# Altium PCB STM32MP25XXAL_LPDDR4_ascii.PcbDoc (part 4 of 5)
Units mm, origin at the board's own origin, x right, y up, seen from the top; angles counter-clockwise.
Board outline 125 x 95 mm, 6 copper layers (Top Layer, Signal Layer 1, Signal Layer 2, Signal Layer 3, Signal Layer 4, Bottom Layer), stack 1.403 mm thick; 182 components, 297 nets, 1131 pads, 958 vias.
Unrouted connection lines stored in the file: 5.
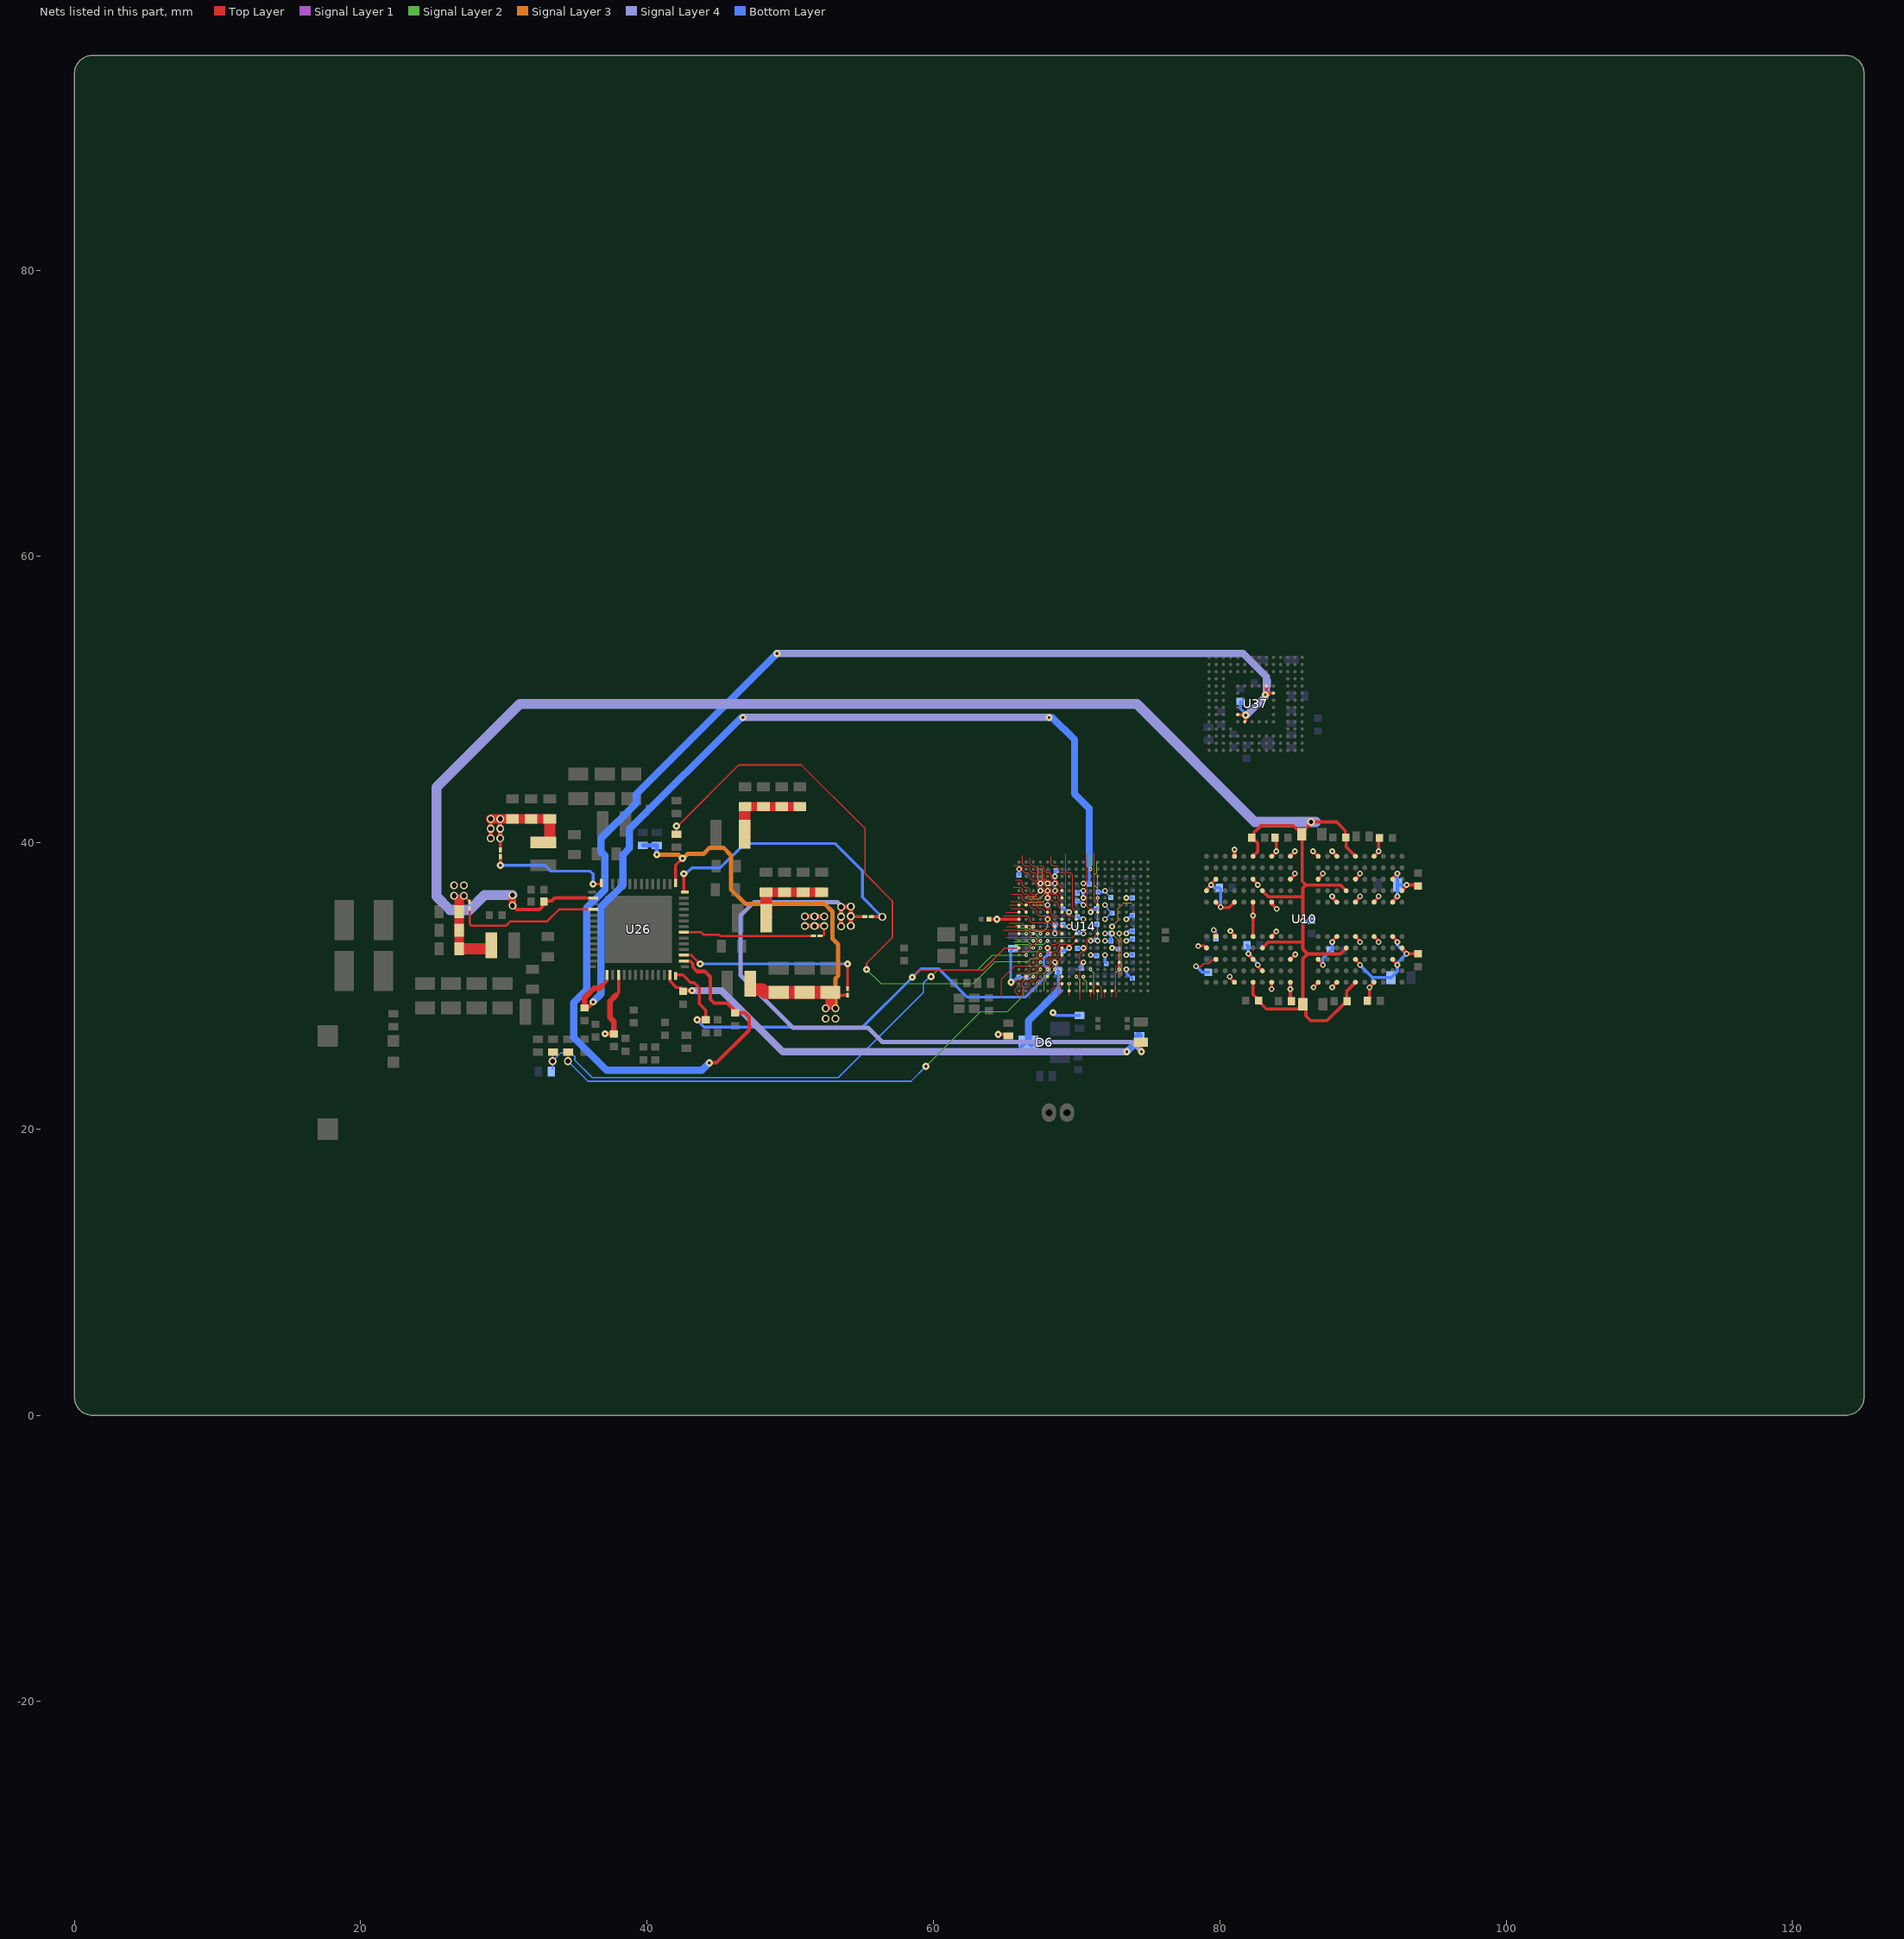
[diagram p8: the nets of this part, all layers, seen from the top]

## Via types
v1: diameter 0.26, hole 0.1, Top Layer to Signal Layer 1, 266 vias
v2: diameter 0.5, hole 0.2, Top Layer to Bottom Layer, 216 vias
v3: diameter 0.26, hole 0.1, Signal Layer 1 to Signal Layer 2, 138 vias
v4: diameter 0.4, hole 0.2, Signal Layer 1 to Signal Layer 4, 99 vias
v5: diameter 0.4, hole 0.2, Top Layer to Bottom Layer, tented both sides, 94 vias
v6: diameter 0.26, hole 0.1, Signal Layer 4 to Bottom Layer, 82 vias
v7: diameter 0.55, hole 0.35, Top Layer to Bottom Layer, 55 vias
v8: diameter 0.55, hole 0.3, Top Layer to Bottom Layer, 7 vias
v9: diameter 0.5, hole 0.2, Signal Layer 1 to Signal Layer 4, 1 vias

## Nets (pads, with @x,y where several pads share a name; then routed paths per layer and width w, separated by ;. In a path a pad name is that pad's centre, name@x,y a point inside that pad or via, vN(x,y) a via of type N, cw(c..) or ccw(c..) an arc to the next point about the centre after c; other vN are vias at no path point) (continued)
PF5: U14.P7 | length 5
  Top Layer w0.075: 66.2,29.125 66.2,29.416 66.224,29.44 66.224,29.755 66.367,29.897 66.575,29.897 66.725,30.048 66.725,30.253 66.873,30.401 67.078,30.401 67.225,30.547 67.225,30.753 67.372,30.899 67.66,30.899 67.662,30.897 68.074,30.897 68.224,31.047 68.224,31.252 68.372,31.4 68.577,31.4 68.732,31.555 68.732,31.75 68.968,31.986 68.968,32.143 U14.P7@68.975,32.15
PF6: U14.U5 | length 2.3
  Top Layer w0.075: 66.725,29.15 66.74,29.165 66.74,29.542 66.732,29.55 66.732,29.75 66.875,29.892 66.886,29.892 66.891,29.897 67.075,29.897 67.225,30.047 67.225,30.253 67.372,30.4 67.578,30.4 67.816,30.638 67.963,30.638 U14.U5@67.975,30.65
PF7: U14.V7 | length 1
  Top Layer w0.075: 68.7,29.25 68.732,29.282 68.732,29.761 68.962,29.991 68.962,30.137 U14.V7@68.975,30.15
PF8: U14.U7 | length 1.8
  Top Layer w0.075: 68.2,29.275 68.232,29.307 68.232,29.75 68.383,29.901 68.578,29.901 68.732,30.055 68.732,30.256 68.965,30.488 68.965,30.64 U14.U7@68.975,30.65
PF9: U14.T6 | length 1.8
  Signal Layer 2 w0.075: 67.725,29.65 67.725,30.253 67.891,30.418 67.891,30.566 v3(68.475,31.15)
  other v1: 68.475,31.15
PF10: U14.L9 | length 5.1
  Top Layer w0.075: 65.675,32.4 66.578,32.4 66.725,32.548 66.725,32.753 66.872,32.9 67.078,32.9 67.225,33.047 67.225,33.253 67.373,33.4 69.725,33.4 U14.L9@69.975,33.65
PF11: U14.T4 | length 1.8
  Signal Layer 2 w0.075: 65.95,30.4 66.175,30.625 66.536,30.625 66.75,30.839 66.811,30.839 66.873,30.901 67.226,30.901 v3(67.475,31.15)
  other v1: 67.475,31.15
PF12: U14.L7 | length 4.2
  Top Layer w0.075: 64.875,33.9 68.578,33.9 68.628,33.85 68.775,33.85 U14.L7@68.975,33.65
PF13: U14.H2 | length 1.2
  Top Layer w0.075: 65.4,35.4 66.225,35.4 U14.H2@66.475,35.15
PF14: U14.G7 | length 5.2
  Top Layer w0.075: 66.226,39.117 66.226,38.753 66.226,38.547 66.372,38.4 66.55,38.4 66.551,38.399 66.578,38.399 66.724,38.253 66.724,38.226 ; U14.G7@68.973,35.652 68.947,35.678 68.947,35.835 68.732,36.05 68.732,36.245 68.578,36.399 68.312,36.399 68.225,36.486 68.225,36.753 68.078,36.9 67.872,36.9 67.725,37.047 67.725,37.252 67.577,37.401 67.372,37.401 67.225,37.547 67.225,37.753 67.077,37.901 66.872,37.901 66.726,38.047 66.726,38.225 ; 66.724,38.226 66.726,38.225
PF15: U14.G5 | length 1
  Signal Layer 3 w0.075: 66.967,35.65 v4(67.975,35.65)
  other v1: 67.975,35.65
PG0: U14.T5 | length 2
  Signal Layer 2 w0.075: 67.226,29.601 67.226,30.253 67.373,30.401 67.578,30.401 67.726,30.548 67.726,30.901 v3(67.975,31.15)
  other v1: 67.975,31.15
PG1: U14.R4 | length 1.8
  Signal Layer 2 w0.075: 65.799,31.401 67.226,31.401 v3(67.475,31.65)
  other v1: 67.475,31.65
PG2: U14.M7 | length 7
  Top Layer w0.075: 64.75,29.159 64.75,30.458 65.692,31.4 66.575,31.4 66.725,31.55 66.725,31.764 ; 66.736,31.764 66.736,31.786 66.851,31.901 67.078,31.901 67.225,32.048 67.225,32.253 67.372,32.4 68.078,32.4 68.225,32.547 68.225,32.753 68.372,32.899 68.58,32.899 68.816,33.135 68.96,33.135 U14.M7@68.975,33.15
PG3: U14.H12 | length 4.6
  Top Layer w0.075: 70.725,39.199 70.725,35.547 70.872,35.401 71.224,35.401 U14.H12@71.475,35.15
PG4: U14.N7 | length 5.8
  Top Layer w0.075: 65.9,29.175 65.9,29.372 65.725,29.547 65.725,29.753 65.88,29.907 66.075,29.907 66.226,30.058 66.226,30.253 66.38,30.407 66.575,30.407 66.718,30.55 66.718,30.561 66.722,30.566 66.722,30.75 66.872,30.9 67.078,30.9 67.225,31.047 67.225,31.253 67.372,31.4 67.637,31.4 67.64,31.397 67.828,31.397 67.831,31.4 68.077,31.4 68.225,31.547 68.225,31.753 68.372,31.899 68.577,31.899 68.724,32.047 68.724,32.313 68.889,32.478 68.889,32.529 68.975,32.614 U14.N7@68.975,32.65
PG5: U14.K1 | length 0.8
  Top Layer w0.075: 65.15,34.15 U14.K1@65.975,34.15
PG6: U14.K2 | length 1.3
  Top Layer w0.075: 65.282,34.393 66.232,34.393 U14.K2@66.475,34.15
PG7: U14.E7 | length 2.7
  Top Layer w0.075: 67.421,38.4 67.422,38.399 67.578,38.399 67.725,38.253 67.725,38.047 67.872,37.9 68.078,37.9 68.225,37.752 68.225,37.547 68.373,37.399 68.578,37.399 68.732,37.245 68.732,37.05 68.963,36.819 68.963,36.704 U14.E7@68.993,36.674
PG8: U14.E5 | length 1.6
  Signal Layer 3 w0.075: 66.614,36.083 67.408,36.083 v4(67.975,36.65)
  other v1: 67.975,36.65
PG9: U14.G2 | length 1.2
  Top Layer w0.075: 65.375,35.925 65.407,35.893 66.075,35.893 66.218,35.75 66.218,35.707 66.25,35.675 66.275,35.65 U14.G2@66.475,35.65
PG10: U14.F5 | length 1.5
  Signal Layer 3 w0.075: 66.565,35.868 67.647,35.868 67.928,36.15 v4(67.975,36.15)
  other v1: 67.975,36.15
PG11: U14.F7 | length 4.2
  Top Layer w0.075: 66.725,38.962 66.725,38.547 66.872,38.4 66.874,38.4 66.875,38.399 67.078,38.399 67.224,38.253 67.224,38.048 67.372,37.901 67.577,37.901 67.725,37.752 67.725,37.547 67.872,37.4 68.078,37.4 68.225,37.253 68.225,37.05 68.225,37.047 68.372,36.901 68.374,36.901 68.376,36.899 68.578,36.899 68.732,36.745 68.732,36.55 68.955,36.327 68.955,36.212 U14.F7@68.993,36.174
PG12: U14.H7 | length 5.5
  Top Layer w0.075: 65.625,38.425 65.839,38.425 65.863,38.4 66.077,38.4 66.226,38.252 66.226,38.047 66.373,37.9 66.578,37.9 66.725,37.753 66.725,37.547 66.872,37.4 67.078,37.4 67.225,37.253 67.225,37.047 67.372,36.901 67.577,36.901 67.725,36.753 67.725,36.547 67.872,36.4 68.078,36.4 68.224,36.253 68.224,36.001 68.326,35.899 68.578,35.899 68.732,35.745 68.732,35.55 68.96,35.322 68.96,35.165 U14.H7@68.973,35.152
PG13: U14.J7 | length 5
  Top Layer w0.075: 65.7,37.4 65.871,37.4 65.872,37.399 66.078,37.399 66.225,37.252 66.225,37.047 66.373,36.9 66.578,36.9 66.725,36.753 66.725,36.547 66.872,36.4 67.078,36.4 67.225,36.252 67.225,36.047 67.372,35.9 67.578,35.9 67.726,35.752 67.726,35.547 67.872,35.4 68.078,35.4 68.225,35.253 68.225,35.047 68.372,34.901 68.584,34.901 68.806,34.678 68.947,34.678 U14.J7@68.975,34.65
PG14: U14.H5 | length 3.5
  Top Layer w0.075: 65.55,36.925 65.576,36.899 66.078,36.899 66.225,36.753 66.225,36.547 66.372,36.4 66.578,36.4 66.725,36.253 66.725,36.047 66.872,35.9 67.078,35.9 67.225,35.753 67.225,35.546 67.372,35.4 67.578,35.4 67.816,35.162 67.963,35.162 U14.H5@67.975,35.15
PG15: U14.E4 | length 1.2
  Signal Layer 3 w0.075: 66.475,36.25 67.075,36.25 v4(67.475,36.65)
  other v1: 67.475,36.65
PH2: U14.L14 | length 3.1
  Signal Layer 3 w0.075: v4(72.475,33.65) 72.975,33.15 72.975,30.78
  other v1: 72.475,33.65
PH3: U14.K14 | length 2.5
  Signal Layer 3 w0.075: v4(72.475,34.15) 72.475,34.159 72.875,34.559 72.875,35.375 73.3,35.8 73.853,35.8
  other v1: 72.475,34.15
PH4: U14.G12 | length 3.8
  Top Layer w0.075: 71.226,39.299 71.226,35.899 U14.G12@71.475,35.65
PH5: U14.M9 | length 5.5
  Top Layer w0.075: 65.875,30.9 66.578,30.9 66.725,31.047 66.725,31.253 66.872,31.4 67.077,31.4 67.224,31.547 67.224,31.65 ; 67.226,31.65 67.226,31.753 67.372,31.899 68.077,31.899 68.224,32.047 68.224,32.252 68.372,32.399 68.577,32.399 68.724,32.547 68.724,32.746 68.879,32.901 69.725,32.901 U14.M9@69.975,33.15
PH6: U14.L15 | length 3
  Signal Layer 3 w0.075: v4(72.975,33.65) 73.008,33.617 73.008,33.392 73.136,33.264 ; 73.137,30.714 73.137,33.264
  other v1: 72.975,33.65
PH7: U14.L12 | length 5.5
  Top Layer w0.075: 70.225,29.05 70.241,29.066 70.241,29.541 70.226,29.557 70.226,30.475 70.226,31.363 70.225,31.364 70.225,32.252 70.371,32.399 70.577,32.399 70.724,32.546 70.724,32.752 70.725,32.753 70.725,33.252 70.873,33.399 71.225,33.399 U14.L12@71.475,33.65
PH8: U14.M12 | length 4.6
  Signal Layer 3 w0.075: v4(71.475,33.15) 71.475,37.775
  other v1: 71.475,33.15
PH9: U14.W8 | length 0.3
  Top Layer w0.075: 69.475,29.325 U14.W8@69.475,29.65
PH10: U14.U10 | length 1.2
  Signal Layer 2 w0.075: v1(70.475,30.65) 70.475,30.443 70.519,30.399 70.578,30.399 70.724,30.253 70.724,29.566
  other v3: 70.475,30.65
PH11: U14.T11 | length 1.7
  Signal Layer 2 w0.075: v3(70.975,31.15) 70.975,31.1 71.2,30.875 71.2,29.518
  other v1: 70.975,31.15
PH12: U14.V8 | length 0.6
  Signal Layer 2 w0.075: 69.475,29.6 v3(69.475,30.15)
  other v1: 69.475,30.15
PH13: U14.U9 | length 1.2
  Signal Layer 2 w0.075: v3(69.975,30.65) 70.225,30.4 70.225,29.572
  other v1: 69.975,30.65
PI0: U14.H1 | length 0.9
  Top Layer w0.075: 65.05,35.175 65.075,35.15 U14.H1@65.975,35.15
PI1: U14.J9 | length 5.6
  Top Layer w0.075: 68.2,39.035 68.2,38.778 68.224,38.753 68.224,38.501 68.326,38.399 68.578,38.399 68.728,38.25 68.728,38.054 68.877,37.905 69.073,37.905 69.224,37.753 69.224,35.048 69.372,34.901 69.724,34.901 U14.J9@69.975,34.65
PI2: U14.J5 | length 2.6
  Signal Layer 3 w0.075: 66.175,34.225 66.675,34.225 67.091,33.809 67.663,33.809 67.975,34.121 v4(67.975,34.65)
  other v1: 67.975,34.65
PI3: U14.H9 | length 4.5
  Top Layer w0.075: 69.226,39.197 69.226,38.047 69.372,37.9 69.578,37.9 69.724,37.753 69.724,35.4 U14.H9@69.975,35.15
PI4: U14.G1 | length 0.7
  Top Layer w0.075: 65.325,35.625 65.35,35.65 U14.G1@65.975,35.65
PI5: U14.K7 | length 4.9
  Top Layer w0.075: 65.476,36.399 66.078,36.399 66.226,36.252 66.226,36.047 66.38,35.892 66.575,35.892 66.718,35.75 66.718,35.739 66.722,35.734 66.722,35.55 66.872,35.4 67.078,35.4 67.225,35.253 67.225,35.047 67.372,34.901 68.077,34.901 68.224,34.753 68.224,34.55 68.249,34.526 68.249,34.524 68.372,34.401 68.649,34.401 68.87,34.18 68.945,34.18 U14.K7@68.975,34.15
PI6: U14.D4 | length 1.3
  Signal Layer 3 w0.075: 67.323,38.375 67.323,37.356 67.475,37.204 v4(67.475,37.15)
  other v1: 67.475,37.15
PI7: U14.D5 | length 1.2
  Signal Layer 3 w0.075: 67.625,38.225 67.625,37.5 v4@67.975,37.15
  other v1: 67.975,37.15
  other v4: 67.975,37.15
PI8: U14.N4 | length 1.4
  Signal Layer 2 w0.075: 66.2,32.4 67.225,32.4 v3(67.475,32.65)
  other v1: 67.475,32.65
PI9: U14.K6 | length 4
  Top Layer w0.075: 64.9,34.925 64.926,34.899 66.578,34.899 66.724,34.753 66.724,34.575 66.726,34.574 66.726,34.547 66.872,34.401 68.078,34.401 68.316,34.162 68.463,34.162 U14.K6@68.475,34.15
PI10: U14.B11 | length 1
  Signal Layer 2 w0.075: v3(70.975,38.15) 70.975,39.15
  other v1: 70.975,38.15
PI11: U14.F12 | length 2.7
  Signal Layer 2 w0.075: 71.395,38.656 71.395,37.923 71.226,37.753 71.226,37.047 71.475,36.797 v3(71.475,36.15)
  other v1: 71.475,36.15
PMIC_WAKEUPn: R46.1 U14.P4 | length 42.1
  Top Layer w0.1: R46.1@42.048,40.587 42.048,41.081 46.399,45.432 50.777,45.432 55.214,40.995 55.214,37.847 57.138,35.924 57.138,33.388 55.328,31.578 v2(55.328,31.139)
  Signal Layer 2 w0.075: v2@55.325,31.15 56.325,30.15 62.775,30.15 64.34,31.715 66.616,31.715 66.801,31.899 67.225,31.899 v3(67.475,32.15)
  other v1: 67.475,32.15
  other v2: 42.048,41.172
PWR_CPU_ON: R60.1 R272.2 U14.P2 | length 39.3
  Top Layer w0.1: v7(33.398,24.739) 33.412,24.753 33.412,25.368 R60.1@33.428,25.384
  Signal Layer 2 w0.075: v2(59.825,30.65) 60.275,31.1 63.05,31.1 64.1,32.15 v1(66.475,32.15)
  Bottom Layer w0.1: R272.2@33.37,24.205 33.399,24.234 v7@33.399,24.737 ; v7(33.398,24.739) 33.959,25.3 34.725,25.3 34.95,25.075 34.95,24.8 36.166,23.584 53.344,23.584 59.297,29.537 59.297,30.197 v2@59.8,30.7
  other v3: 66.475,32.15
PWR_ON: R2.1 U14.U3 | length 37.4
  Top Layer w0.1: v7(34.473,24.739) 34.478,24.744 R2.1@34.478,25.384
  Signal Layer 2 w0.075: v2(59.475,24.375) 63.3,28.2 65.175,28.2 66.325,29.35 66.325,29.87 66.226,29.97 66.226,30.282 66.369,30.425 66.664,30.425 66.804,30.566 66.84,30.566 66.925,30.65 v3(66.975,30.65)
  Bottom Layer w0.1: v7(34.473,24.739) 35.878,23.334 58.434,23.334 v2(59.475,24.375)
  other v1: 66.975,30.65
PZ0: U14.L5 | length 2.4
  Signal Layer 2 w0.075: 65.894,33.875 66.347,33.875 66.372,33.899 66.578,33.899 66.742,33.736 66.839,33.736 66.875,33.7 67.072,33.7 67.372,33.4 67.726,33.4 v3(67.975,33.65)
  other v1: 67.975,33.65
PZ1: U14.M4 | length 1.8
  Signal Layer 2 w0.075: 65.825,33.4 67.078,33.4 67.087,33.391 67.292,33.185 67.44,33.185 v3(67.475,33.15)
  other v1: 67.475,33.15
PZ2: U14.M3 | length 1.3
  Signal Layer 2 w0.075: 65.71,33.281 65.722,33.281 65.76,33.243 66.794,33.243 66.852,33.185 66.94,33.185 v3(66.975,33.15)
  other v1: 66.975,33.15
PZ3: U14.M5 | length 2.5
  Signal Layer 2 w0.075: 65.625,33.075 66.625,33.075 66.799,32.901 67.703,32.901 67.953,33.15 v3(67.975,33.15)
  other v1: 67.975,33.15
PZ4: U14.L4 | length 1.8
  Signal Layer 2 w0.075: 65.868,34.04 66.279,34.04 66.303,34.064 66.647,34.064 66.711,34 66.772,34 66.872,33.901 67.224,33.901 v3(67.475,33.65)
  other v1: 67.475,33.65
PZ5: U14.N3 | length 1.4
  Signal Layer 2 w0.075: 65.678,32.9 66.578,32.9 66.724,32.753 66.724,32.749 66.803,32.671 66.954,32.671 v3(66.975,32.65)
  other v1: 66.975,32.65
PZ6: U14.K3 | length 1.3
  Signal Layer 2 w0.075: 65.755,34.225 66.23,34.225 66.235,34.229 66.715,34.229 66.72,34.225 66.85,34.225 66.925,34.15 v3(66.975,34.15)
  other v1: 66.975,34.15
PZ7: U14.L1 | length 0.8
  Top Layer w0.075: 65.225,33.65 U14.L1@65.975,33.65
PZ8: U14.L3 | length 2
  Top Layer w0.075: 65.083,33.4 66.725,33.4 U14.L3@66.975,33.65
PZ9: U14.L2 | length 0.5
  Signal Layer 2 w0.075: 65.95,33.65 v3(66.475,33.65)
  other v1: 66.475,33.65
UCPD1_CC1: U14.W13 | length 0.4
  Top Layer w0.075: 71.95,29.225 71.975,29.25 U14.W13@71.975,29.65
UCPD1_CC2: U14.W14 | length 0.5
  Top Layer w0.075: 72.475,29.2 U14.W14@72.475,29.65
USB3DR_DM: U14.V12 | length 1.1
  Top Layer w0.075: U14.V12@71.475,30.15 71.725,29.9 71.725,29.125
USB3DR_DP: U14.W12 | length 0.6
  Top Layer w0.075: 71.45,29.05 71.475,29.075 U14.W12@71.475,29.65
USB3DR_TXRTUNE: U14.R15 | length 2.6
  Top Layer w0.075: 72.775,29.203 72.775,29.518 72.71,29.584 72.71,30.032 72.725,30.047 72.725,31.274 72.952,31.502 72.952,31.627 U14.R15@72.975,31.65
USBH_HS_DM: U14.V11 | length 0.9
  Top Layer w0.075: U14.V11@70.975,30.15 71.225,29.9 71.225,29.375
USBH_HS_DP: U14.W11 | length 0.4
  Top Layer w0.075: 70.975,29.225 U14.W11@70.975,29.65
USBH_HS_TXRTUNE: U14.T15 | length 1.5
  Signal Layer 1 w0.075: 72.725,29.75 72.725,30.9 v1(72.975,31.15)
VBAT: C87.2 D6.3 U14.R6 | length 7.3
  Bottom Layer w0.2: v6(68.475,31.65) 68.475,31.634 68.575,31.534 C87.2@68.575,31.1 ; 68.725,29.654 C87.2@68.725,31.05
  Bottom Layer w0.3: D6.3@66.076,25.692 66.426,26.042 D6.3@66.626,26.042
  Bottom Layer w0.5: D6.3@66.825,25.975 66.626,26.174 66.626,27.555 68.725,29.654
  other v1: 68.475,31.65
  other v4: 68.475,31.65
VDD1_DDR: C40.2 C62.2 C63.2 C64.2 C65.2 C66.2 C67.2 C68.2 U10.F1 U10.F12 U10.G4 U10.G9 U10.T4 U10.T9 U10.U1 U10.U12 U26.44 | length 135.6
  Top Layer w0.15: U10.F12@82.325,39.05 U10.F12@82.34,39.066
  Top Layer w0.21: 35.673,36.139 U26.44@36.228,36.139
  Top Layer w0.22: U10.F1@82.325,30.25 82.325,29.393 82.555,29.163 82.555,29.09 83.26,28.385 85.59,28.385 C63.2@85.8,28.595 ; U10.F12@82.325,39.05 82.65,39.375 82.65,39.975 82.445,40.18 82.387,40.18 82.3,40.267 82.387,40.354 82.387,40.697 82.875,41.185 85.15,41.185 85.415,40.92 85.539,40.92 C62.2@85.75,40.71 ; U10.G9@82.95,36.65 83.37,36.23 85.8,36.23 ; U10.G4@82.975,32.65 83.39,33.065 85.8,33.065 ; C63.2@85.8,28.582 C63.2@85.8,28.72 85.8,31.891 86.138,32.229 ; C63.2@85.812,28.582 86.01,28.385 86.01,27.899 86.323,27.586 86.323,27.58 87.502,27.58 88.688,28.765 88.755,28.765 88.871,28.881 C67.2@88.871,28.973 ; U10.T4@88.825,32.65 88.404,32.229 86.125,32.229 85.8,32.555 85.8,33.065 ; U10.T9@88.825,36.65 88.429,37.046 86.014,37.046 ; C67.2@89.016,29.118 C67.2@88.871,28.973 ; U10.U1@89.475,30.25 89.475,30.245 88.871,29.641 C67.2@88.871,28.973 ; U10.U12@89.475,39.056 88.825,39.706 88.825,40.36 88.768,40.416 88.768,40.841 88.16,41.45 v8(86.375,41.45) 86.312,41.387 86.312,41.297 85.935,40.92 85.75,40.735 C62.2@85.75,40.71 ; C62.2@85.75,40.71 85.75,37.31 86.014,37.046 ; 85.8,33.065 85.8,36.831 86.014,37.046
  Top Layer w0.25: v7(30.6,35.612) 30.873,35.339 32.473,35.339 32.718,35.584 32.718,35.774 32.833,35.889 C40.2@32.903,35.889 ; C40.2@32.908,35.774 33.063,35.929 33.338,35.929 33.548,36.139 35.673,36.139
  Top Layer w0.5: v7(30.6,35.612) v7@30.6,36.335
  Signal Layer 4 w0.7: v7(30.598,36.337) 28.644,36.337 27.608,35.301 26.236,35.301 25.282,36.255 25.282,43.871 31.098,49.687 74.213,49.687 82.45,41.45 86.725,41.45
  Bottom Layer w0.22: v5(85.8,34.525) C68.2@86.425,34.525
VDD2_DDR: C41.2 C50.2 C51.2 C52.2 C53.1 C54.1 C55.1 C56.1 C57.1 C58.1 C59.1 C60.1 C61.1 C175.1 C192.1 C200.2 C202.2 C211.1 C284.1 C304.1 C306.1 L5.2 LNK8.2 R94.2 U10.A4 U10.A9 U10.AA3 U10.AA5 U10.AA8 U10.AA10 U10.AB4 U10.AB9 U10.B3 U10.B5 U10.B8 U10.B10 U10.D1 U10.D5 U10.D8 U10.D12 U10.F3 U10.F5 U10.F8 U10.F10 U10.G2 U10.H1 U10.H5 U10.H8 U10.H12 U10.K1 U10.K3 U10.K10 U10.K12 U10.N1 U10.N3 U10.N10 U10.N12 U10.R1 U10.R5 U10.R8 U10.R12 U10.U3 U10.U5 U10.U8 U10.U10 U10.W1 U10.W5 U10.W8 U10.W12 U14.F16 U14.J16 U14.L16 U14.M16 U14.P16 U14.T16 | length 56
  Top Layer w0.09: v5(78.35,31.375) 78.375,31.35 78.681,31.35 78.872,31.54 79.203,31.54 79.49,31.827 79.701,31.827 U10.B3@79.725,31.85
  Top Layer w0.15: v7(27.196,36.304) 27.598,35.902 LNK8.2@27.598,35.862 ; v5@79.575,33.925 79.575,33.857 79.686,33.746 79.686,33.488 U10.B5@79.725,33.45
  Top Layer w0.2: v5(78.5,32.775) 78.529,32.804 78.882,32.804 79.036,32.65 U10.A4@79.075,32.65 ; v5(80.7,30.65) 80.7,30.575 U10.D1@81.025,30.25 ; U10.H5@83.625,33.45 83.625,33.475 v5(83.95,33.8)
  Top Layer w0.22: U10.A9@79.09,36.665 U10.A9@79.075,36.65 79.075,36.725 79.4,37.05 79.4,37.125 U10.B10@79.725,37.45 U10.B10@79.725,37.445 ; U10.B8@79.725,35.83 v5@80.025,35.53 ; v5@80.025,35.51 80.059,35.476 80.219,35.476 80.65,35.475 U10.D8@81.025,35.85 ; v5@80.733,33.831 80.96,33.604 80.96,33.55 81.025,33.485 U10.D5@81.025,33.45 ; v5@82,32.17 82.32,31.85 U10.F3@82.325,31.85 ; U10.F5@82.325,33.45 82.325,34.576 82.337,34.588 82.337,34.898 v5(82.325,34.91) U10.F8@82.325,35.85 ; U10.F10@82.325,37.45 82.325,37.421 82.64,37.105 v5@82.64,37.07 ; v5(82.65,31.45) 82.684,31.416 82.684,31.341 U10.G2@82.975,31.05 ; v5@83.6,29.76 83.625,29.785 U10.H1@83.625,30.25 ; U10.H8@83.625,35.81 83.625,35.725 v5(83.975,35.375) ; U10.H12@83.625,39.05 83.95,39.375 83.95,40.25 C52.2@83.85,40.35 ; v5(84.925,29.77) 84.925,29.01 C54.1@85,28.935 ; v5@84.925,29.775 U10.K1@84.925,30.25 ; U10.K10@84.925,37.45 84.93,37.45 85.25,37.77 v5@85.25,37.785 ; U10.K12@84.925,39.05 84.925,39.075 v5(85.25,39.4) ; U10.K3@84.925,31.85 v5(85.275,32.2) ; v5@86.477,39.448 U10.N12@86.875,39.05 ; v5@86.55,29.92 86.875,30.245 U10.N1@86.875,30.25 ; U10.N3@86.875,31.833 87.165,31.543 87.165,31.485 v5(87.2,31.45) ; U10.N10@86.875,37.45 86.88,37.45 v5@87.2,37.77 ; v5@87.85,29.92 88.175,30.245 U10.R1@88.175,30.25 ; v5@87.85,33.12 88.175,33.445 U10.R5@88.175,33.45 ; v5(87.85,36.25) 87.884,36.216 87.884,36.141 U10.R8@88.175,35.85 ; v5(87.85,39.4) 88.175,39.075 U10.R12@88.175,39.05 ; U10.U3@89.474,31.845 89.765,31.554 89.765,31.485 v5(89.8,31.45) ; U10.U5@89.475,33.45 89.8,33.125 v5@89.8,33.12 ; U10.U8@89.475,35.85 89.475,35.885 89.54,35.95 89.54,35.953 89.8,36.213 v5(89.8,36.25) ; U10.U10@89.475,37.45 89.48,37.45 v5@89.8,37.77 ; C55.1@90.3,28.95 90.445,29.095 90.445,29.244 90.45,29.249 v5(90.45,29.9) 90.45,29.92 U10.W1@90.775,30.245 ; U10.W1@90.775,30.238 U10.W1@90.775,30.245 ; U10.W1@90.775,30.25 U10.W1@90.775,30.245 ; U10.W5@90.775,33.45 90.775,33.445 v5@91.1,33.12 ; U10.W8@90.775,35.87 91.065,36.161 91.065,36.216 v5(91.1,36.25) ; U10.W12@90.775,39.05 91.095,39.37 v5@91.1,39.37 ; v5(91.1,39.4) C53.1@91.1,40.23 ; U10.AA3@92.075,31.85 92.075,31.823 92.4,31.498 v5(92.4,31.45) ; U10.AA5@92.075,33.45 92.075,33.422 92.4,33.097 v5(92.4,33.05) ; U10.AA8@92.075,35.85 92.075,35.884 92.4,36.209 v5(92.4,36.25) ; U10.AA10@92.075,37.45 92.075,37.485 92.4,37.81 v5(92.4,37.85) ; U10.AB4@92.725,32.65 92.965,32.41 92.965,32.322 v5@93.034,32.253 ; U10.AB9@92.725,36.65 93.015,36.941 93.015,37.016 v5(93.05,37.05) 93.77,37.05 C56.1@93.85,36.97 ; v5@93.052,32.248 C57.1@93.836,32.248
  Top Layer w0.28: U10.D12@81.025,39.05 v5@81.025,39.5
  Top Layer w0.64: C202.2@26.873,32.589 C41.2@26.873,33.889 C200.2@26.873,35.189 ; 26.873,35.634 26.873,36.064
  Top Layer w0.8: C202.2@27.098,32.589 L5.2@28.873,32.589
  Bottom Layer w0.2: v4(73.475,31.15) 73.475,30.875 73.75,30.6 73.825,30.6 C284.1@73.9,30.525 C284.1@73.9,30.45 ; v4(73.475,33.15) 73.491,33.15 73.551,33.209 73.834,33.209 C306.1@73.9,33.275 ; v4(73.475,36.15) C304.1@73.9,36.15
  Bottom Layer w0.22: v4(73.475,32.15) 73.5,32.175 C192.1@73.9,32.175 ; v4(73.475,33.65) 73.65,33.825 C211.1@73.9,33.825 C211.1@73.925,33.825 ; v1(73.475,34.65) 73.486,34.65 73.576,34.74 73.593,34.74 73.603,34.75 73.655,34.75 73.765,34.86 73.835,34.86 C175.1@73.9,34.925 ; v5(78.35,31.375) 78.775,30.95 C60.1@79.2,30.95 ; v5(79.4,37.05) 79.6,36.85 C61.1@79.975,36.85 80.054,36.771 v5@80.054,35.504 ; v5(79.57,33.9) 79.725,33.745 R94.2@79.725,33.35 R94.2@79.725,33.325 ; C59.1@81.9,32.85 81.975,32.775 v5@81.975,32.225 ; v5(82,32.25) 82.23,32.02 82.23,31.976 82.56,31.647 82.56,31.589 82.65,31.499 v5(82.65,31.45) ; v5(87.2,31.45) 87.2,31.925 C58.1@87.725,32.45 C58.1@87.75,32.475 ; C58.1@87.75,32.45 87.85,32.55 v5(87.85,33.05) ; v5(89.8,31.45) 90.675,30.575 ; v5@90.45,29.9 90.675,30.125 90.675,30.575 ; 91.1,30.575 90.675,30.575 ; 91.125,30.575 C50.2@91.95,30.575 ; C50.2@91.95,30.55 92.4,31 v5(92.4,31.45) ; v5@92.35,31.45 92.35,31.551 v5@93.025,32.225 ; v5(92.4,33.05) 92.4,32.85 v5@93.025,32.225 ; v5(92.4,36.25) C51.2@92.4,37.075 ; v5(92.4,37.85) 92.4,37.15 C51.2@92.425,37.125 ; C51.2@92.425,37.1 92.475,37.05 v5(93.05,37.05) ; v5(93.05,32.25) v5@93.025,32.225
  other v1: 73.475,31.15 73.475,32.15 73.475,33.15 73.475,33.65 73.475,36.15
  other v4: 73.475,34.65
  other v5: 83.625,29.77 86.55,29.9 87.85,29.9 89.8,33.05 91.1,33.05 80.735,33.831 80.05,35.5 82.65,37.05 85.25,37.85 87.2,37.85 89.8,37.85 83.95,39.4 86.5,39.4 81.025,39.525
  other v6: 73.475,31.15 73.475,32.15 73.475,33.15 73.475,33.65 73.475,34.65 73.475,36.15
  other v7: 26.521,36.304 26.521,37.029 27.196,37.029
VDD3V3_USB: C156.2 R286.1 U26.13 | length 36
  Top Layer w0.21: U26.13@41.598,30.769 41.598,30.339 42.061,29.876 42.316,29.876 42.318,29.874 42.388,29.874 42.523,29.739 C156.2@42.523,29.669
  Top Layer w0.3: C156.2@42.523,29.669 v2(43.133,29.669)
  Signal Layer 4 w0.5: v2@43.134,29.668 45.207,29.668 49.475,25.4 v2(73.5,25.4)
  Bottom Layer w0.5: v2(73.5,25.4) 74.275,26.175 74.275,26.52 74.28,26.525 R286.1@74.375,26.525
VDD_DDR_FB: LNK8.1 U26.46 | length 10.2
  Top Layer w0.15: LNK8.1@27.598,35.412 27.598,34.329 27.715,34.212 30.165,34.212 30.465,34.512 31.135,34.512 31.137,34.514 33.025,34.514 33.85,35.339 U26.46@36.228,35.339
VDD_EMMC: C9.2 C117.2 C190.1 U26.16 U37.E6 U37.F5 U37.J10 U37.K9 | length 97.6
  Top Layer w0.2: U37.E6@81.25,48.95 v2@81.8,48.95 ; U37.F5@81.751,48.447 81.751,48.459 81.8,48.508 v2(81.8,48.915) ; v2(83.176,50.347) v2@83.251,50.422 ; U37.J10@83.251,50.947 83.251,50.517 83.243,50.509 83.243,50.43 v2@83.251,50.422 ; U37.K9@83.751,50.447 83.371,50.447 83.338,50.414 83.259,50.414 v2@83.251,50.422
  Top Layer w0.21: U26.16@42.568,31.739 42.998,31.739 43.186,31.551 43.186,31.326 43.332,31.18
  Top Layer w0.25: 43.33,31.177 43.496,31.011 44.026,31.011 44.423,30.614 44.423,29.064 44.698,28.789 45.593,28.789 46.148,28.234 C190.1@46.148,28.164 ; v2(44.35,24.625) 44.841,24.625 47.123,26.907 47.123,27.807 46.81,28.12 C190.1@46.164,28.12
  Signal Layer 4 w0.5: v2(49.075,53.225) 81.625,53.225 83.25,51.6 83.25,50.375 v2@83.2,50.325 ; v2(81.8,48.915) 81.888,48.915 83.176,50.203 v2(83.176,50.347)
  Bottom Layer w0.2: C9.2@81.451,49.863 81.451,49.357 v2@81.72,49.088 ; v2@83.186,50.338 83.186,51.023 C117.2@83.311,51.148
  Bottom Layer w0.5: v2(44.35,24.625) 43.825,24.1 37.182,24.1 34.875,26.407 34.875,28.825 35.775,29.725 35.775,35.445 37.054,36.724 37.054,39.096 36.775,39.375 36.775,40.309 39.252,42.786 39.252,43.402 v2(49.075,53.225)
VDD_SDCARD: C142.1 U26.4 | length 5.1
  Top Layer w0.21: 37.823,29.339 37.998,29.514 U26.4@37.998,30.769
  Top Layer w0.3: v2(37.063,26.649) C142.1@37.673,26.649
  Top Layer w0.4: C142.1@37.673,26.649 37.673,27.532 37.408,27.797 37.408,28.924 37.823,29.339
VDDA1V8_AON: C189.2 C234.2 U14.N1 U14.N5 U26.14 | length 43.6
  Top Layer w0.1: v2(58.525,30.6) 58.536,30.6 59.041,31.104 63.444,31.104 64.976,32.636 65.323,32.636 65.961,32.636 U14.N1@65.975,32.65
  Top Layer w0.21: U26.14@41.998,30.769 42.508,30.769 43.046,30.231 43.286,30.231 43.643,29.873 43.643,28.741 44.098,28.286 C189.2@44.098,27.629
  Top Layer w0.3: v2(43.488,27.629) C189.2@44.098,27.629
  Bottom Layer w0.2: v2@43.469,27.63 43.974,27.126 55.051,27.126 v2(58.525,30.6) 59.125,31.2 60.375,31.2 62.364,29.211 66.397,29.211 68.07,30.884 68.07,31.221 67.953,31.338 67.82,31.338 67.713,31.445 67.713,31.945 67.82,32.052 67.878,32.052 67.995,32.169 C234.2@68.07,32.245 ; v4(67.975,32.65) 67.975,32.35 67.995,32.33 67.995,32.32 C234.2@68.065,32.25
  other v1: 67.975,32.65
  other v6: 67.975,32.65
VDDCORE: C16.2 C22.2 C23.2 C24.2 C183.2 C195.1 C196.2 C201.2 C203.1 C213.2 C215.2 C289.2 C299.2 C300.2 L2.2 LNK2.2 R11.1 U14.B1 U14.C6 U14.G10 U14.H11 U14.J1 U14.J10 U14.K11 U14.L10 U14.N8 U14.N10 | length 58.9
  Top Layer w0.2: C22.2@50.673,42.514 C22.2@50.721,42.562 ; 54.598,34.839 LNK2.2@55.214,34.839 ; C201.2@63.9,34.65 v2(64.425,34.65) ; v2@64.425,34.625 64.45,34.65 U14.J1@65.975,34.65 ; R11.1@74.475,26.075 74.525,26.025 v2(74.525,25.4) v2@74.525,25.375
  Top Layer w0.3: v7(53.554,34.163) v7(53.554,34.838) v7(53.554,35.513) 54.229,35.513 v7@54.229,34.163
  Top Layer w0.64: C183.2@46.848,42.514 C24.2@48.123,42.514 C23.2@49.398,42.514 C22.2@50.673,42.514
  Top Layer w0.8: L2.2@46.813,40.339 L2.2@46.813,40.589 C183.2@46.813,42.312
  Signal Layer 4 w0.3: v7@53.6,35.55 53.3,35.85 47.475,35.85 46.516,34.891 46.516,30.747 50.187,27.075 55.425,27.075 56.42,26.08 73.845,26.08 v2(74.525,25.4)
  Bottom Layer w0.2: C215.2@65.975,37.75 v4(65.975,38.15) ; v4(68.475,37.65) 68.475,37.98 C16.2@68.55,38.055 ; C300.2@69.05,32.425 69.125,32.5 69.309,32.5 69.459,32.65 v1(69.475,32.65) ; C195.1@70.05,32.625 70.434,32.625 70.459,32.65 v1(70.474,32.649) ; C289.2@70.05,33.725 70.083,33.692 70.417,33.692 70.459,33.65 v1(70.475,33.65) ; C196.2@70.05,34.825 70.125,34.75 70.359,34.75 70.459,34.65 v1(70.475,34.65) ; C213.2@70.05,35.925 70.125,35.85 70.275,35.85 v1(70.475,35.65) ; v1(70.975,34.15) 70.991,34.15 71.073,34.232 71.327,34.232 C203.1@71.4,34.305 ; v1(70.975,35.15) 70.991,35.15 71.171,35.33 71.325,35.33 C299.2@71.4,35.405
  other v1: 68.475,37.65 65.975,38.15
  other v4: 69.475,32.65 70.474,32.649 70.475,33.65 70.975,34.15 70.475,34.65 70.975,35.15 70.475,35.65
  other v6: 69.475,32.65 70.474,32.649 70.475,33.65 70.975,34.15 70.475,34.65 70.975,35.15 70.475,35.65 68.475,37.65 65.975,38.15
  other v7: 54.224,34.193 54.224,34.868 54.224,35.543
VDDCORE_FB: LNK2.1 U26.28 | length 20.6
  Top Layer w0.2: U26.28@42.568,36.539 v2(42.568,37.839) ; LNK2.1@55.664,34.839 v7@56.274,34.839
  Bottom Layer w0.2: v2@42.544,37.837 42.601,37.894 42.775,37.894 43.128,38.248 45.108,38.248 46.801,39.941 53.147,39.941 55.049,38.039 55.049,36.178 v7@56.407,34.82 ; v2@42.549,37.84 42.606,37.898 42.78,37.898 43.133,38.251
  other v7: 56.431,34.822
VDDCPU: C26.2 C27.2 C28.2 C177.1 C191.1 C194.2 C283.2 C287.2 L3.2 LNK4.1 U14.E13 U14.G13 U14.J13 U14.L13 U14.M13 | length 14.1
  Top Layer w0.2: LNK4.1@29.748,39.489 v7(29.748,40.312)
  Top Layer w0.3: v7(29.073,40.312) v7(29.073,40.987) v7(29.073,41.662) v7(29.748,41.662) v7(29.748,40.987) v7(29.748,40.312)
  Top Layer w0.64: v7(29.073,41.662) 29.073,41.664 C27.2@30.598,41.664 C28.2@31.898,41.664 C26.2@33.198,41.664
  Top Layer w0.8: L3.2@32.748,40.014 33.198,40.014 33.198,41.312
  Bottom Layer w0.1: v1(71.975,34.65) 72.275,34.95 72.35,34.95 C177.1@72.475,35.075 ; v1(71.975,35.65) 72.168,35.457 72.168,35.382 C177.1@72.475,35.075 ; v6@71.977,36.65 71.977,36.605 72.065,36.517 72.065,36.492 72.255,36.302 72.255,36.3 C191.1@72.38,36.175 ; C177.1@72.475,35.05 C177.1@72.475,35.075
  Bottom Layer w0.2: C287.2@71.5,36.55 71.875,36.55 v1(71.975,36.65) ; v1(71.975,33.65) C194.2@72.4,33.65 ; v6@72,33.125 C283.2@72.4,33.125 ; C283.2@72.375,33.1 C283.2@72.4,33.125 ; C194.2@72.4,33.675 C194.2@72.4,33.65 ; C194.2@72.425,33.65 C194.2@72.4,33.65 ; C283.2@72.4,33.125 C194.2@72.4,33.65
  other v1: 71.975,33.15
  other v4: 71.975,33.15 71.975,33.65 71.975,34.65 71.975,35.65 71.975,36.65
  other v6: 71.975,33.15 71.975,33.65 71.975,34.65 71.975,35.65 71.975,36.65
VDDCPU_FB: LNK4.2 U26.42 | length 8.6
  Top Layer w0.2: v2(29.748,38.429) LNK4.2@29.748,39.039 ; v2(36.223,37.114) U26.42@36.793,37.114
  Bottom Layer w0.2: v2(29.748,38.429) 32.878,38.427 33.293,38.012 36.022,38.012 36.224,37.81 v2@36.224,37.112
VDDGPU: C1.2 C2.2 C3.2 C4.2 C5.2 C34.2 C35.2 C36.2 C37.2 L4.2 LNK7.2 U14.M11 U14.N14 U14.P11 U14.P13 U14.R10 | length 11.6
  Top Layer w0.15: LNK7.2@52.073,33.489 52.08,33.497 52.283,33.497 52.371,33.584 v7(52.371,34.177)
  Top Layer w0.2: C35.2@52.448,36.531 C35.2@52.496,36.484
  Top Layer w0.3: v7(51.021,34.177) v7(51.696,34.177) v7(52.371,34.177) ; v7(51.021,34.852) v7(51.696,34.852) v7(52.371,34.852)
  Top Layer w0.64: C37.2@48.298,36.539 C36.2@49.598,36.539 C34.2@50.898,36.539 C35.2@52.198,36.539
  Top Layer w0.8: L4.2@48.323,34.739 48.323,36.212
  Bottom Layer w0.2: C2.2@70.25,31.225 70.315,31.29 70.315,31.491 v1(70.474,31.65) ; v6(70.975,32.15) 71.355,32.15 C1.2@71.4,32.105 ; v1(70.975,33.149) 70.991,33.149 71.023,33.181 71.376,33.181 C3.2@71.4,33.205 ; v1(71.975,32.15) 71.975,31.675 C4.2@72.075,31.575 ; v1(72.475,32.65) 72.825,32.65 C5.2@72.9,32.575
  other v1: 70.975,32.15
  other v4: 70.474,31.65 70.975,32.15 71.975,32.15 72.475,32.65 70.975,33.149
  other v6: 70.474,31.65 71.975,32.15 72.475,32.65 70.975,33.149
VDDGPU_FB: LNK7.1 U26.21 | length 9.3
  Top Layer w0.15: U26.21@42.448,33.739 43.781,33.739 43.958,33.562 45.038,33.562 45.111,33.489 LNK7.1@51.623,33.489
VDDIO: C17.2 C19.2 C186.2 C187.2 C197.2 C205.2 C219.2 C307.1 L6.2 LNK11.2 R27.2 R67.2 R260.2 R261.2 U14.D6 U14.E6 U14.E10 U14.F10 U14.H8 U14.K8 U14.L6 U26.29 | length 40.2
  Top Layer w0.2: U26.29@41.998,37.184 41.998,38.437 v2(42.473,38.912) ; C186.2@52.798,29.539 52.983,29.354 LNK11.2@53.998,29.354 ; v2(64.525,26.6) 64.538,26.613 65.213,26.613 R27.2@65.225,26.625
  Top Layer w0.64: 52.798,28.664 C186.2@52.798,29.094
  Top Layer w0.9: L6.2@47.248,29.739 48.048,29.739 48.248,29.539 C187.2@49.198,29.539 C19.2@50.998,29.539 C186.2@52.798,29.539
  Signal Layer 3 w0.3: v2@40.683,39.165 42.198,39.165 42.449,38.914 v2@42.474,38.914 ; v2@42.474,38.911 42.528,38.911 42.839,39.222 43.942,39.222 44.372,39.651 45.33,39.651 45.854,39.127 45.854,36.739 46.855,35.738 52.398,35.738 52.95,35.186 52.95,33.294 53.35,32.894 53.35,30.711 53.151,30.513 v7(53.15,28.424)
  Bottom Layer w0.1: v4(68.475,36.65) v4(68.475,37.15)
  Bottom Layer w0.2: C17.2@68.045,37.15 v4(68.475,37.15) ; v6(68.341,28.116) 68.383,28.116 68.558,27.941 R67.2@70.199,27.941 ; v1(68.475,33.65) 68.475,34.2 C197.2@68.55,34.275 ; C197.2@68.5,34.275 68.525,34.25 C197.2@68.575,34.2 ; C205.2@69.025,35.375 69.1,35.3 69.325,35.3 v1(69.475,35.15) ; C307.1@69.05,34.275 69.175,34.15 v1(69.475,34.15) ; C219.2@70.05,36.475 70.214,36.639 v6@70.464,36.639 ; v6(70.474,36.149) 70.463,36.16 70.463,36.203 70.45,36.215 70.45,36.583 70.464,36.596 v6@70.464,36.639 ; v4(70.475,36.65) v6@70.464,36.639
  Bottom Layer w0.3: R260.2@39.709,39.82 40.684,39.82 40.673,39.81 40.673,39.178 v2@40.663,39.168
  other v1: 70.474,36.149 68.475,36.65 70.475,36.65 68.475,37.15
  other v2: 40.682,39.166
  other v4: 68.475,33.65 69.475,34.15 69.475,35.15 70.474,36.149
  other v6: 68.475,33.65 69.475,34.15 69.475,35.15 68.475,36.65 70.475,36.65 68.475,37.15
  other v7: 52.475,27.699 53.15,27.699 52.475,28.424
  other v9: 68.35,28.125
VDDIO_FB: LNK11.1 U26.17 | length 13.4
  Top Layer w0.15: U26.17@42.568,32.139 43.098,32.139 43.701,31.536 v2(43.713,31.536)
  Top Layer w0.2: LNK11.1@53.998,29.804 v2(53.998,31.539)
  Bottom Layer w0.15: v2@53.996,31.534 v2@53.999,31.537
  Bottom Layer w0.2: v2(43.713,31.536) v2@53.996,31.534
VDDIO_SDCARD: C210.2 C217.1 U14.D10 U26.2 | length 63
  Top Layer w0.21: 36.857,30.012 37.198,30.353 U26.2@37.198,30.769
  Top Layer w0.3: C217.1@35.623,28.519 35.668,28.564 35.957,28.564 36.233,28.84 v2(36.233,28.876)
  Top Layer w0.4: C217.1@35.623,28.459 35.623,28.519 35.623,29.154 36.297,29.829 36.673,29.829 36.857,30.012
  Signal Layer 4 w0.5: v2(46.7,48.75) 46.707,48.757 68.068,48.757 v2(68.075,48.75)
  Bottom Layer w0.2: v6(70.475,37.15) 70.875,37.15 C210.2@70.9,37.125 ; C210.2@70.875,37.096 70.875,38.475
  Bottom Layer w0.5: v2@36.214,28.877 36.775,29.438 36.775,35.501 38.318,37.044 38.318,39.173 38.761,39.616 38.761,40.93 46.581,48.75 v2(46.7,48.75) ; v2(68.075,48.75) 68.3,48.75 69.85,47.2 69.85,43.425 70.875,42.4 70.875,38.475
  other v1: 70.475,37.15
  other v4: 70.475,37.15
VREF+: C248.2 C250.2 R269.2 U14.U2 | length 4.9
  Top Layer w0.075: v2@65.375,30.3 65.782,30.3 65.875,30.392 66.07,30.392 66.316,30.638 66.463,30.638 U14.U2@66.475,30.65
  Bottom Layer w0.2: v2@65.4,30.325 65.4,32.45 R269.2@65.55,32.6 ; v2(65.425,30.25) 65.506,30.25 65.781,30.525 65.875,30.525 C248.2@65.95,30.6 ; C248.2@65.955,30.605 65.96,30.6 66.565,30.6 C250.2@66.57,30.605
pads on no net: U10.A1 U10.A2 U10.A8 U10.A11 U10.A12 U10.AA1 U10.AA2 U10.AA4 U10.AA9 U10.AA11 U10.AA12 U10.AB1 U10.AB2 U10.AB11 U10.AB12 U10.B1 U10.B12 U10.G11 U10.H3 U10.J5 U10.K5 U10.K8 U10.N5 U10.N8 U10.P2 U10.P4 U10.P5 U10.P8 U10.P9 U10.P11 U10.R2 U10.R3 U10.R4 U10.R9 U10.R10 U10.R11 U10.T2 U10.U2 U10.U4 U10.U9 U10.U11 U10.V2 U10.V3 U10.V4 U10.V9 U10.V10 U10.V11 U10.W3 U10.W10 U10.Y2 U10.Y3 U10.Y4 U10.Y9 U10.Y10 U10.Y11 U14.E19 U14.F19 U14.G17 U14.G19 U14.H17 U14.H19 U14.J18 U14.K17 U14.K18 U14.K19 U14.L18 U14.L19 U14.M18 U14.M19 U14.N18 U14.N19 U14.P1 U14.P17 U14.P18 U14.P19 U14.R17 U14.R19 U14.T12 U37.A1 U37.A2 U37.A7 U37.A8 U37.A9 U37.A10 U37.A11 U37.A12 U37.A13 U37.A14 U37.B1 U37.B7 U37.B8 U37.B9 U37.B10 U37.B11 U37.B12 U37.B13 U37.B14 U37.C1 U37.C3 U37.C5 U37.C7 U37.C8 U37.C9 U37.C10 U37.C11 U37.C12 U37.C13 U37.C14 U37.D1 U37.D2 U37.D3 U37.D4 U37.D12 U37.D13 U37.D14 U37.E1 U37.E2 U37.E3 U37.E5 U37.E8 U37.E9 U37.E10 U37.E12 U37.E13 U37.E14 U37.F1 U37.F2 U37.F3 U37.F10 U37.F12 U37.F13 U37.F14 U37.G1 U37.G2 U37.G3 U37.G10 U37.G12 U37.G13 U37.G14 U37.H1 U37.H2 U37.H3 U37.H12 U37.H13 U37.H14 U37.J1 U37.J2 U37.J3 U37.J12 U37.J13 U37.J14 U37.K1 U37.K2 U37.K3 U37.K6 U37.K7 U37.K10 U37.K12 U37.K13 U37.K14 U37.L1 U37.L2 U37.L3 U37.L12 U37.L13 U37.L14 U37.M1 U37.M2 U37.M3 U37.M7 U37.M8 U37.M9 U37.M10 U37.M11 U37.M12 U37.M13 U37.M14 U37.N1 U37.N3 U37.N6 U37.N7 U37.N8 U37.N9 U37.N10 U37.N11 U37.N12 U37.N13 U37.N14 U37.P1 U37.P2 U37.P7 U37.P8 U37.P9 U37.P10 U37.P11 U37.P12 U37.P13 U37.P14
copper on no net: | length 0.4
  Signal Layer 1 w0.1: 73.712,22.092 73.715,22.095
  Signal Layer 2 w0.075: 69.22,45.77 69.225,45.775
  Signal Layer 4 w0.09: 54.67,69.65 54.673,69.647 ; 54.673,69.127 54.75,69.05
  Bottom Layer w0.09: 29.625,93.625 29.8,93.8

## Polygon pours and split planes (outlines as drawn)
5V_STLK on Signal Layer 4 "5V_STLK" (solid, pour order 297): 125,95.201 125,0.3 0,0.3 0,95.201
VDD2_DDR on Signal Layer 4 "VDD_DDR" (solid, remove dead copper, pour order 293): 73.2,42.125 73.2,31.05 74.562,29.687 93.05,29.813 93.05,39.425 84.537,39.425 75.839,48.123 30.252,48.123 25.645,43.516 25.645,36.278 26.317,35.606 27.615,35.606 28.618,36.609 28.618,41.913 29.454,42.75 72.575,42.75
VDDCPU on Signal Layer 4 "VDDCPU" (solid, remove dead copper, pour order 292): 46.237,38.475 69.4,38.475 71.025,36.85 71.025,32.9 73.2,32.9 73.2,42.125 72.687,42.638 40.002,42.638 40.002,42.651 39.116,43.538 30.242,43.538 28.618,41.913 28.618,39.888 28.718,39.988 38.515,39.988 39.454,39.05 39.542,39.138 45.574,39.138
VDDGPU on Signal Layer 4 "VDDGPU" (solid, remove dead copper, pour order 272): 53.029,33.196 55.325,30.9 70.275,30.9 70.275,32.1 70.725,32.1 70.725,33.35 73.25,33.35 73.25,28.075 49.673,28.075 46.8,30.879 46.8,34.699 47.529,35.428 53.029,35.428
3V3 on Signal Layer 4 "3V3_L4" (solid, remove dead copper, pour order 294): 33.955,30.677 32.353,29.075 15.11,29.075 15.11,19.532 37.399,19.532 37.399,30.677
VDDCORE on Signal Layer 4 "VDDCORE" (solid, remove dead copper, pour order 291): 53.144,33.175 55.394,30.925 70.975,30.925 70.975,36.735 69.335,38.375 53.144,38.375
GND on Top Layer "GND_L01_P283" (solid, pour order 283): 0.118,95.007 125.307,95.007 125.307,-0.293 0.468,-0.293
VDDIO on Top Layer "VDDIO" (solid, pour order 280): 41.893,36.909 41.893,38.707 42.428,39.242 42.61,39.242 43.048,38.803 43.048,38.262 42.348,37.562 42.348,36.909
VDDCORE on Top Layer "VDDCORE_TOP" (solid, pour order 278): 51.905,42.834 54.787,39.952 54.787,33.725 54.792,33.72 53.338,33.72 52.793,34.265 52.793,38.966 52.42,39.339 50.773,39.339 46.413,39.339 46.403,42.834
NetL6_1 on Top Layer "NetL13_1" (solid, pour order 282): 44.273,32.002 44.736,31.539 45.998,31.539 45.998,29.239 45.996,29.237 44.699,29.237 44.699,30.861 44.273,31.287
3V3 on Top Layer "3V3" (solid, pour order 281): 23.785,26.687 23.96,26.512 30.308,26.512 31.61,27.814 31.61,28.662 23.986,28.662 23.785,28.462
VDDGPU on Top Layer "VDDGPU_TOP" (solid, pour order 279): 52.501,33.739 52.643,33.881 52.643,36.859 47.923,36.859 47.923,33.739
VDDCPU on Top Layer "VDDCPU_TOP" (solid, pour order 277): 28.71,41.984 28.71,40.137 29.233,39.614 33.648,39.614 33.643,39.619 33.643,41.984
5V_STLK on Top Layer "5V_VIN" (solid, pour order 259): 33.408,33.759 34.065,33.759 34.248,33.942 34.248,33.602 33.765,33.119 33.408,33.119
GND on Signal Layer 3 "GND" (solid, pour order 298): 125,95 125,0 0,0 0,95
1V8 on Signal Layer 3 "1V8_L04_P295" (solid, pour order 295): 66.275,34.3 71.55,34.3 71.55,27.275 73.9,27.275 86.65,27.275 86.65,52.875 76.525,52.875 76.525,49.35 39.4,49.35 39.4,39.55 66.275,39.55
VDDIO on Signal Layer 3 "VDDIO" (solid, remove dead copper, pour order 252): 69.775,35.95 70.025,36.2 70.025,36.9 70.8,36.9 70.8,33.9 70.525,33.9 70.525,26.35 53.129,26.35 51.952,27.527 51.952,29.784 53.344,31.176 63.125,31.176 63.125,34.2 68.275,34.2 68.275,34.3 69.275,34.3 69.275,35.95
GND on Signal Layer 2 "GND_L03_P299" (solid, pour order 299): -0.045,94.712 124.993,94.712 124.993,-0.288 0.304,-0.288
VDDIO on Signal Layer 2 "VDDIO_L03_P258" (solid, pour order 258): 69,37.35 69,37 69.275,36.725 69.65,36.725 69.75,36.825 69.75,37.35 70.675,37.35 70.675,33.35 67.95,33.35 67.95,37.35
GND on Signal Layer 1 "gnd" (solid, pour order 236): -0.171,94.778 125,94.778 125,-0.222 0.003,-0.222
GND on Bottom Layer "GND" (solid, remove dead copper, pour order 257): 0,95.1 125,95.1 125,0.1 0,0.1

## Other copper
Top Layer:
  rectangle net VDD2_DDR: 26.553,31.939 29.523,33.739
Signal Layer 1:
  text "2" at 121.175,16.8 h1.2 r90
Signal Layer 2:
  text "3" at 121.175,18.05 h1.2 r90
Signal Layer 3:
  text "4" at 121.175,19.3 h1.2 r90
Signal Layer 4:
  text "5" at 121.175,20.55 h1.2 r90
Bottom Layer:
  text "R" at 257.217,60.102 h1.2
  text "2" at 258.744,60.102 h1.2
  text "6" at 259.911,60.088 h1.2
  text "7" at 260.989,60.085 h1.2
  text "0" at 264.831,60.088 h1.2
  text "R" at 265.999,60.102 h1.2
  text "6" at 121.175,21.8 h1.2 r90

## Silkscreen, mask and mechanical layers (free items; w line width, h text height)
Top Overlay:
  text "J" at 48.264,80.005 h15
Bottom Overlay:
  lines w0.1: 55.225,72.525 55.225,47.925 76.7,47.925 76.7,72.528 55.225,72.528 ; 69.675,44.8 70.025,44.45 ; 70.025,47.85 70.025,44.45 ; 70.375,44.8 70.025,44.45
  text "J" at 31.1,87.65 h1.2
Top Paste:
  text ".Layer_Name" at 27.423,-26.172 h1.2
  text ".GTP" at 69.118,-26.172 h1.2
Bottom Paste:
  text ".GBP" at 57.907,-26.196 h1.2
  text ".Layer_Name" at 99.221,-26.196 h1.2
Top Solder:
  text ".Layer_Name" at 27.423,-26.172 h1.2
  text ".GTS" at 69.118,-26.172 h1.2
Bottom Solder:
  text ".GBS" at 57.907,-26.196 h1.2
  text ".Layer_Name" at 99.221,-26.196 h1.2
M1-Board Shape:
  the board outline again, w0.1
M14-Top Assembly:
  text ".Layer_Name" at 27.423,-26.172 h1.2
  text ".GM14" at 69.118,-26.172 h1.2
M15-Bottom Assembly:
  text ".GM15" at 57.907,-26.196 h1.2
  text ".Layer_Name" at 99.221,-26.196 h1.2
Drill Drawing:
  drawing of 411 lines, arcs and shapes, not listed
  text "MINIMUN PARAMETERS" at 150.3,143.65 h1.2
  text "PCB SPECIFICATIONS :" at -1.425,142.95 h1.2
  text "A.   MATERIAL :" at -1.425,138.95 h1.2
  text "FR-4" at 37.075,138.95 h1.2
  text "TG-170" at 53.575,138.95 h1.2
  text "X  TG-150" at 71.825,138.95 h1.2
  text "TG-140" at 87.825,138.95 h1.2
  text "DEFAULT" at 150.3,138.15 h1.2
  text "B.   MATERIAL FAMILY :" at -1.425,135.95 h1.2
  text "N/A" at 37.075,135.95 h1.2
  text "C.   SOLDERMASK COLOR :" at -1.425,132.95 h1.2
  text "GREEN" at 37.075,132.95 h1.2
  text "X  BLUE" at 53.575,132.95 h1.2
  text "RED" at 71.825,132.95 h1.2
  text "BLACK" at 87.825,132.95 h1.2
  text "TRACKS : 0.100mm           / GAPS : 0.100mm" at 150.3,132.4 h1.2
  text "D.   SILKSCREEN COLOR :" at -1.425,129.95 h1.2
  text "X  WHITE" at 37.075,129.95 h1.2
  text "YELLOW" at 53.575,129.95 h1.2
  text "BLACK" at 71.825,129.95 h1.2
  text "E.   SURFACE FINISH :" at -1.425,126.95 h1.2
  text "X  ENIG" at 37.075,126.95 h1.2
  text "IMMERSION SILVER" at 53.575,126.95 h1.2
  text "IMMERSION TIN" at 87.825,126.95 h1.2
  text "UNDER MPU" at 150.3,125.9 h1.2
  text "HASL" at 37.075,123.95 h1.2
  text "HASL (PB-FREE)" at 53.575,123.95 h1.2
  text "GOLDEN FINGER" at 87.825,123.95 h1.2
  text "F.   IMPEDANCE CONTROL :" at -1.425,120.95 h1.2
  text "NO" at 37.075,120.95 h1.2
  text "X  YES  (SEE IMPEDANCE TABLE FOR DETAIL INFORMATION)" at 53.575,120.95 h1.2
  text "TRACKS : 0.075mm           / GAPS : 0.082mm" at 150.3,120.15 h1.2
  text "G.   THROUGH VIA :" at -1.425,117.95 h1.2
  text "PLUG THE VIAS WHICH ARE COVERED WITH SOLDERMASK ONE OR TWO SIDE." at 37.075,117.95 h1.2
  text "PLUG MATERIAL :" at 37.075,114.95 h1.2
  text "X  SOLDERMASK" at 62.575,114.95 h1.2
  text "NON-CONDUCTIVE EPOXY." at 87.825,114.95 h1.2
  text "UNDER DDR" at 150.3,113.9 h1.2
  text "H.   STACK-UP :" at -1.425,111.95 h1.2
  text "SEE LAYER STACK-UP SEQUENCE FOR OVERALL THICKNESS." at 37.075,111.95 h1.2
  text "TRACKS : 0.090mm           / GAPS : 0.090mm" at 150.3,108.15 h1.2
  text "Layer" at 135.6,101.625 h2
  text "Name" at 143.964,101.625 h2
  text "Material" at 160.132,101.625 h2
  text "Thickness" at 174.666,101.625 h2
  text "Constant" at 186.602,101.625 h2
  text "Board Layer Stack" at 197.654,101.625 h2
  text "Top Overlay" at 143.964,97.625 h2
  text "Top Solder" at 143.964,93.625 h2
  text "Solder Resist" at 160.132,93.625 h2
  text "0.025mm" at 174.666,93.625 h2
  text "3.5" at 186.602,93.625 h2
  text "1" at 135.6,89.625 h2
  text "Top Layer" at 143.964,89.625 h2
  text "0.046mm" at 174.666,89.625 h2
  text "Dielectric 1" at 143.964,85.625 h2
  text "0.071mm" at 174.666,85.625 h2
  text "4.21" at 186.602,85.625 h2
  text "2" at 135.598,81.625 h2
  text "Signal Layer 1" at 143.964,81.625 h2
  text "0.035mm" at 174.666,81.625 h2
  text "Dielectric 2" at 143.964,77.625 h2
  text "0.094mm" at 174.666,77.625 h2
  text "4.09" at 186.602,77.625 h2
  text "3" at 135.6,73.625 h2
  text "Signal Layer 2" at 143.964,73.625 h2
  text "0.023mm" at 174.666,73.625 h2
  text "Dielectric 3" at 143.964,69.625 h2
  text "0.865mm" at 174.666,69.625 h2
  text "4.68" at 186.602,69.625 h2
  text "4" at 135.6,65.625 h2
  text "Signal Layer 3" at 143.964,65.625 h2
  text "0.023mm" at 174.666,65.625 h2
  text "Dielectric 4" at 143.964,61.625 h2
  text "0.094mm" at 174.666,61.625 h2
  text "4.09" at 186.602,61.625 h2
  text "5" at 135.6,57.625 h2
  text "Signal Layer 4" at 143.964,57.625 h2
  text "0.035mm" at 174.666,57.625 h2
  text "Dielectric5" at 143.964,53.625 h2
  text "0.071mm" at 174.666,53.625 h2
  text "4.21" at 186.602,53.625 h2
  text "6" at 135.6,49.625 h2
  text "Bottom Layer" at 143.964,49.625 h2
  text "0.046mm" at 174.666,49.625 h2
  text "Bottom Solder" at 143.964,45.625 h2
  text "Solder Resist" at 160.132,45.625 h2
  text "0.025mm" at 174.666,45.625 h2
  text "3.5" at 186.602,45.625 h2
  text "Bottom Overlay" at 143.964,41.625 h2
  text "Symbol" at 136.016,-10.993 h2.4
  text "Count" at 145.405,-10.993 h2.4
  text "Hole Size" at 155.14,-10.993 h2.4
  text "Plated" at 173.374,-10.993 h2.4
  text "Hole Type" at 181.617,-10.993 h2.4
  text "Drill Layer Pair" at 193.617,-10.993 h2.4
  text "Via/Pad" at 216.346,-10.993 h2.4
  text "Pad Shape" at 226.178,-10.993 h2.4
  text "Template" at 239.023,-10.993 h2.4
  text "Hole Tolerance (+)" at 270.138,-10.993 h2.4
  text "Hole Tolerance (-)" at 290.198,-10.993 h2.4
  text "2" at 145.405,-15.13 h2
  text "0.500mm (19.69mil)" at 155.14,-15.13 h2
  text "PTH" at 173.374,-15.13 h2
  text "Round" at 181.617,-15.13 h2
  text "Top Layer - Bottom Layer" at 193.617,-15.13 h2
  text "Pad" at 216.346,-15.13 h2
  text "Rounded" at 226.178,-15.13 h2
  text "r100_130h50r100m105_135(Tol5-5)" at 239.023,-15.13 h2
  text "0.050mm (1.97mil)" at 270.138,-15.13 h2
  text "0.050mm (1.97mil)" at 290.198,-15.13 h2
  text "7" at 145.405,-19.267 h2
  text "0.300mm (11.81mil)" at 155.14,-19.267 h2
  text "PTH" at 173.374,-19.267 h2
  text "Round" at 181.617,-19.267 h2
  text "Top Layer - Bottom Layer" at 193.617,-19.267 h2
  text "Via" at 216.346,-19.267 h2
  text "Rounded" at 226.178,-19.267 h2
  text "v55h30m35" at 239.023,-19.267 h2
  text "55" at 145.405,-23.405 h2
  text "0.350mm (13.78mil)" at 155.14,-23.405 h2
  text "PTH" at 173.374,-23.405 h2
  text "Round" at 181.617,-23.405 h2
  text "Top Layer - Bottom Layer" at 193.617,-23.405 h2
  text "Via" at 216.346,-23.405 h2
  text "Rounded" at 226.178,-23.405 h2
  text "v55h35m40mx40" at 239.023,-23.405 h2
  text "410" at 145.405,-27.542 h2
  text "0.200mm (7.87mil)" at 155.14,-27.542 h2
  text "PTH" at 173.374,-27.542 h2
  text "Round" at 181.617,-27.542 h2
  text "(Mixed)" at 193.617,-27.542 h2
  text "Via" at 216.346,-27.542 h2
  text "Rounded" at 226.178,-27.542 h2
  text "(Mixed)" at 239.023,-27.542 h2
  text "486" at 145.405,-31.68 h2
  text "0.100mm (3.94mil)" at 155.14,-31.68 h2
  text "PTH" at 173.374,-31.68 h2
  text "Round" at 181.617,-31.68 h2
  text "(Mixed)" at 193.617,-31.68 h2
  text "Via" at 216.346,-31.68 h2
  text "Rounded" at 226.178,-31.68 h2
  text "v26h10" at 239.023,-31.68 h2
  text "960 Total" at 145.405,-35.817 h2
M20-Top Sheet Box:
  circle w0.254: c105.427,-32.893 r1.3
  lines w0.254: 81.186,-31.493 89.978,-31.493 86.912,-27.956 cw(c88.716,-26.012) 88.956,-23.371 105.72,-23.371 104.958,-25.657 ; 84.5,-23.124 cw(c86.926,-24.094) 87.163,-21.492 ; 84.539,-23.091 80.193,-33.986 99.515,-33.986 ccw(c99.764,-31.252) 102.313,-32.272 ; 86.279,-27.026 91.701,-33.282 ; 86.533,-27.026 91.838,-33.147 ; 86.533,-26.772 91.838,-32.893 ; 86.631,-25.657 99.624,-25.657 ; 86.66,-26.645 91.965,-32.766 ; 86.787,-26.518 92.092,-32.639 ; 86.914,-26.391 92.219,-32.512 ; 87.041,-26.264 92.346,-32.385 ; 87.096,-24.312 92.401,-30.433 ; 87.164,-21.492 106.614,-21.492 102.314,-32.269 ; 87.168,-26.137 92.418,-32.195 ; 87.168,-25.883 92.473,-32.004 ; 87.168,-25.629 92.473,-31.75 ; 87.168,-24.74 92.473,-30.861 ; 87.295,-25.502 92.6,-31.623 ; 87.295,-25.121 92.6,-31.242 ; 88.667,-31.507 ccw(c88.772,-30.972) 89.069,-30.515 ; 89.753,-25.643 ccw(c89.727,-26.211) 89.397,-26.673 91.762,-29.401 cw(c89.958,-31.345) 90.691,-33.894 ; 96.034,-33.782 98.924,-25.403 ; 96.257,-33.732 99.126,-25.412 ; 96.384,-33.732 99.253,-25.412 ; 96.638,-33.732 99.507,-25.412 ; 96.892,-33.732 99.761,-25.412 ; 97.146,-33.732 100.015,-25.412 ; 97.4,-33.732 100.269,-25.412 ; 97.654,-33.732 100.523,-25.412 ; 97.908,-33.732 100.777,-25.412 ; 98.162,-33.732 101.031,-25.412 ; 98.37,-33.782 101.26,-25.403 ; 101.26,-25.657 104.952,-25.657 ; 104.284,-25.654 105.046,-23.368 ; 104.45,-25.657 105.212,-23.371 ; 104.704,-25.657 105.466,-23.371
  lines w0.3: 18.423,-32.872 78.423,-32.872 ; 18.423,-27.872 78.423,-27.872 ; 18.423,-22.872 78.423,-22.872 ; 58.423,-37.872 58.423,-22.872 ; 78.423,-37.872 78.423,-17.872 ; 96.034,-33.782 98.37,-33.782 ; 18.423,-37.872 108.423,-37.872 108.423,-17.872 18.423,-17.872 18.423,-37.872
